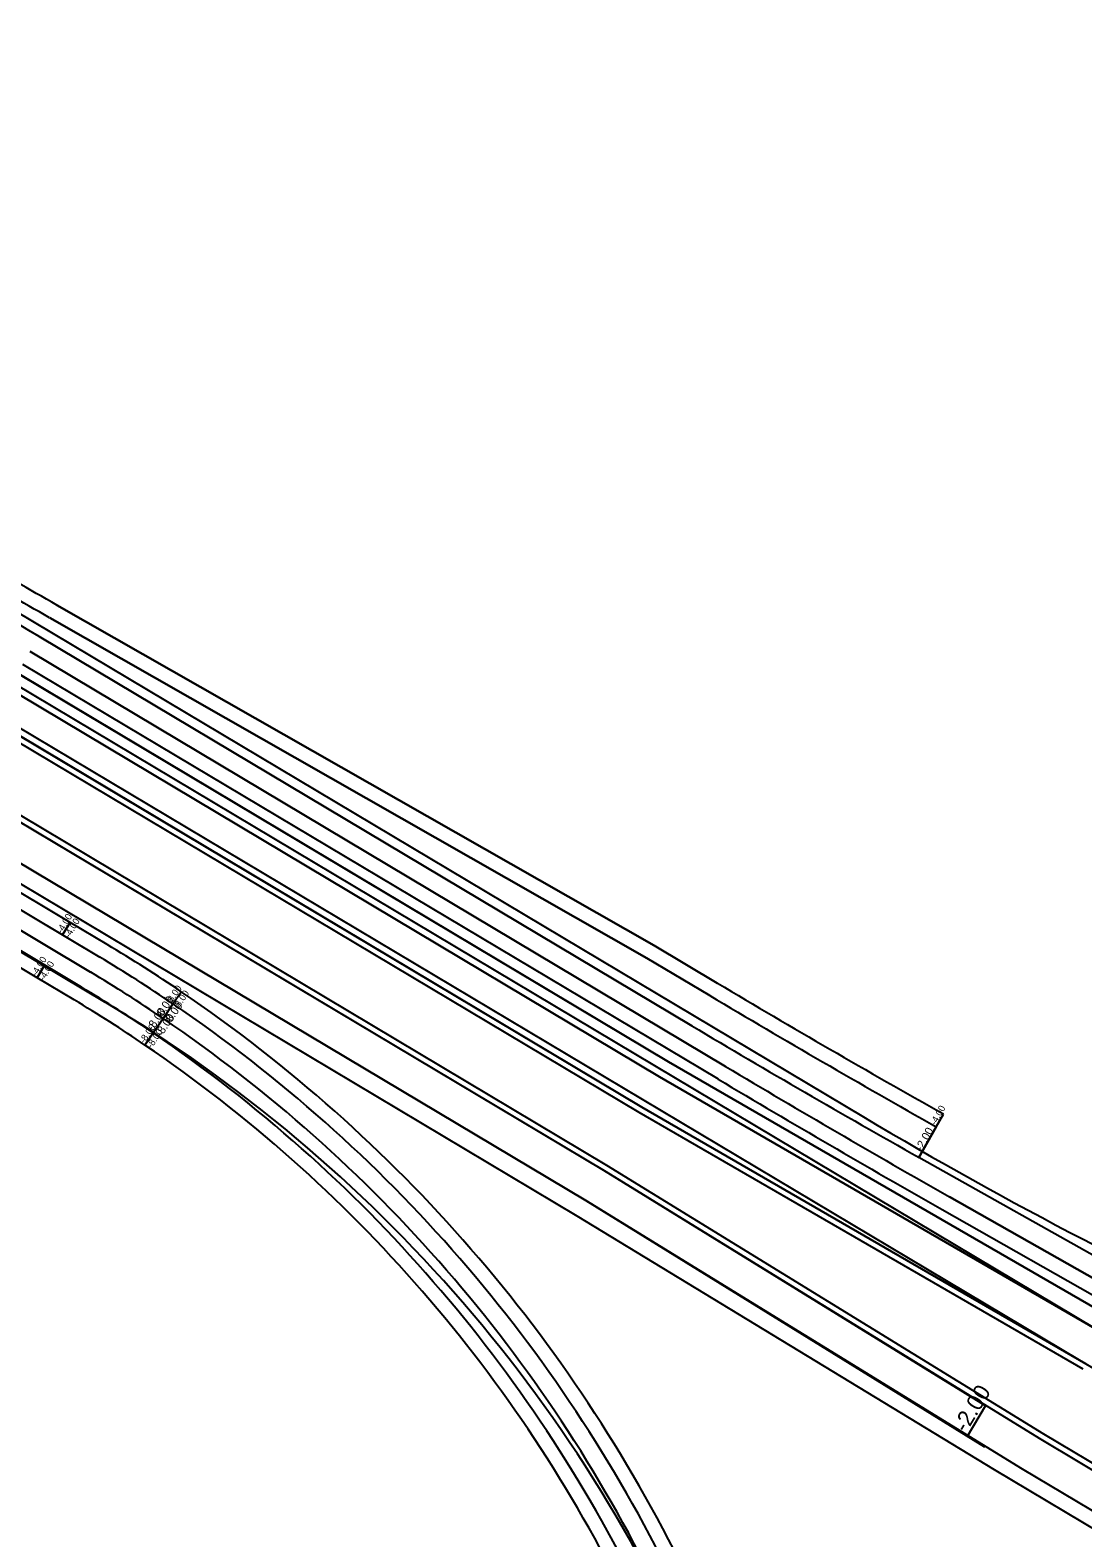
# Model space of a CAD drawing. Extents: x 2342222 to 2351711, y 366548 to 372860.
# Drawn here: x 2347894 to 2348613, y 368410 to 369439 of the extents above; entities that cross this region are included whole.
import ezdxf

# ---------------------------------------------------------------- set-up
doc = ezdxf.new("R2010")
doc.units = 0
for name, color, linetype in [('RD_HC_Cl', 7, 'Continuous'), ('RD_PD_Final_LnLine', 7, 'Continuous'), ('RD_PD_PaveShd', 7, 'Continuous'), ('RD_PD_SuperShp_BL_EB_526', 7, 'Continuous'), ('RD_PD_SuperShp_BL_WB_526', 7, 'Continuous'), ('RD_PD_SuperShp_EB_526', 7, 'Continuous'), ('RD_PD_SuperShp_REL_LINE-3', 7, 'Continuous'), ('RD_PD_SuperShp_Rel_Line-4', 7, 'Continuous'), ('RD_PD_SuperShp_WB_526', 7, 'Continuous')]:
    doc.layers.add(name, color=color, linetype=linetype)

msp = doc.modelspace()

# ---------------------------------------------------------------- linework, layer by layer
at = {"layer": 'RD_HC_Cl'}
msp.add_line((2346606.5, 369804.5), (2348463.1, 368696.8), dxfattribs=at)
msp.add_line((2346606.5, 369804.5), (2348463.1, 368696.8), dxfattribs=at)
msp.add_arc((2349949, 371187.2), 2900, 239.1785, 245.9774, dxfattribs=at)
msp.add_arc((2349949, 371187.2), 2900, 239.1785, 245.9774, dxfattribs=at)
at = {"layer": 'RD_PD_Final_LnLine'}
msp.add_line((2346236.7, 369794.6), (2347945.2, 368775.3), dxfattribs=at)
msp.add_line((2346236.7, 369794.6), (2347945.2, 368775.3), dxfattribs=at)
msp.add_arc((2347432.8, 367916.5), 1000, 22.4559, 59.1785, dxfattribs=at)
msp.add_arc((2347432.8, 367916.5), 1000, 22.4559, 59.1785, dxfattribs=at)
at = {"layer": 'RD_PD_PaveShd'}
for p, q in [((2347103.3, 369419.8), (2348309.7, 368700)), ((2347580.8, 369181.5), (2348330, 368734.5)), ((2348330, 368734.5), (2348633, 368559.4)), ((2348309.8, 368700), (2348612.7, 368524.9))]:
    msp.add_line(p, q, dxfattribs=at)
at = {"layer": 'RD_PD_SuperShp_BL_EB_526'}
for p, q in [((2348273.5, 368639.7), (2346277, 369830.9)), ((2346270.8, 369820.6), (2348267.4, 368629.4)), ((2346351.1, 369814.6), (2348286, 368660.2)), ((2348273.5, 368639.7), (2346338.8, 369794)), ((2347079.5, 369380), (2348286, 368660.2)), ((2348288, 368663.7), (2347081.6, 369383.5)), ((2348286, 368660.2), (2348584, 368476.8)), ((2348286, 368660.2), (2348584, 368476.8)), ((2348586.1, 368480.2), (2348288, 368663.7)), ((2348571.6, 368456.3), (2348273.5, 368639.7)), ((2348571.6, 368456.3), (2348273.5, 368639.7)), ((2348267.4, 368629.4), (2348552.3, 368456.1)), ((2348584, 368476.8), (2351064, 366997.1)), ((2348584, 368476.8), (2349219.5, 368097.6)), ((2349221.6, 368101.1), (2348586.1, 368480.2)), ((2348552.3, 368456.1), (2348815.4, 368299.2)), ((2351051.7, 366976.5), (2348571.6, 368456.3)), ((2348820.5, 368307.8), (2348571.6, 368456.3))]:
    msp.add_line(p, q, dxfattribs=at)
at = {"layer": 'RD_PD_SuperShp_BL_WB_526'}
for p, q in [((2348323.9, 368724.2), (2346306.8, 369927.7)), ((2346294.5, 369907), (2348311.8, 368703.5)), ((2347103.3, 369419.8), (2348309.8, 368700)), ((2348311.8, 368703.5), (2347105.3, 369423.3)), ((2348330, 368734.5), (2347580.8, 369181.5)), ((2347574.6, 369171.2), (2348323.9, 368724.2)), ((2348633, 368559.4), (2348330, 368734.5)), ((2348626.9, 368549), (2348323.9, 368724.2)), ((2348323.9, 368724.2), (2348626.9, 368549)), ((2348309.8, 368700), (2348612.7, 368524.9)), ((2348311.8, 368703.5), (2348614.8, 368528.3)), ((2348614.8, 368528.3), (2348311.8, 368703.5))]:
    msp.add_line(p, q, dxfattribs=at)
at = {"layer": 'RD_PD_SuperShp_EB_526'}
for p, q in [((2348285.9, 368660.3), (2346335.9, 369823.7)), ((2346323.3, 369803.3), (2348273.5, 368639.7)), ((2346323.6, 369803.1), (2348273.5, 368639.7)), ((2348546.3, 368499.6), (2348285.9, 368660.3)), ((2348273.5, 368639.7), (2348545.7, 368471.7)), ((2348273.5, 368639.7), (2348534, 368479)), ((2348534, 368479), (2348546.3, 368499.6))]:
    msp.add_line(p, q, dxfattribs=at)
at = {"layer": 'RD_PD_SuperShp_REL_LINE-3'}
for p, q in [((2347921.7, 368829.6), (2346247.5, 369828.4)), ((2346242.4, 369819.8), (2347916.5, 368821)), ((2346323.7, 369743.4), (2347904.2, 368800.4)), ((2347899.1, 368791.8), (2346318.6, 369734.8)), ((2347877.9, 368844), (2347941.8, 368805.9)), ((2347935.6, 368795.6), (2347871.8, 368833.7)), ((2347871.8, 368833.7), (2347935.6, 368795.6)), ((2347929.5, 368785.3), (2347865.6, 368823.4)), ((2347916.5, 368821), (2347921.7, 368829.6)), ((2347921.7, 368829.6), (2347916.5, 368821)), ((2347946.9, 368814.5), (2347921.7, 368829.6)), ((2347916.5, 368821), (2347941.8, 368805.9)), ((2347904.2, 368800.4), (2347899.1, 368791.8)), ((2347899.1, 368791.8), (2347904.2, 368800.4)), ((2347924.4, 368776.7), (2347899.1, 368791.8)), ((2347904.2, 368800.4), (2347929.5, 368785.3)), ((2347991.8, 368774.1), (2347997.4, 368782.3)), ((2347991.8, 368774.1), (2347997.4, 368782.3)), ((2347991.8, 368774.1), (2347985.1, 368764.1)), ((2347991.8, 368774.1), (2347985.1, 368764.1)), ((2347985.1, 368764.1), (2347978.3, 368754.2)), ((2347978.3, 368754.2), (2347985.1, 368764.1)), ((2347978.3, 368754.2), (2347972.7, 368745.9)), ((2347972.7, 368745.9), (2347978.3, 368754.2))]:
    msp.add_line(p, q, dxfattribs=at)
for radius, start, end in [(1022, 55.8206, 59.1785), (1012, 55.8206, 59.1785), (1012, 55.8206, 59.1785), (1000, 55.8206, 59.1785), (1000, 55.8206, 59.1785), (988, 55.8206, 59.1785), (988, 55.8206, 59.1785), (1022, 26.0841, 55.8206), (978, 55.8206, 59.1785), (1012, 26.0841, 55.8206), (1012, 26.0841, 55.8206), (1000, 26.0841, 55.8206), (1000, 26.0841, 55.8206), (988, 26.0841, 55.8206), (988, 26.0841, 55.8206), (978, 26.0841, 55.8206)]:
    msp.add_arc((2347423.3, 367936.8), radius, start, end, dxfattribs=at)
at = {"layer": 'RD_PD_SuperShp_Rel_Line-4'}
for p, q in [((2347912.6, 369046.2), (2348320.3, 368813.9)), ((2348320.3, 368813.9), (2347912.6, 369046.2)), ((2348315.2, 368805.2), (2347907.7, 369037.5)), ((2347907.7, 369037.5), (2348315.2, 368805.2)), ((2347900.5, 369024.7), (2348345.9, 368759)), ((2347900.5, 369024.7), (2348345.9, 368759)), ((2348345.9, 368759), (2347900.5, 369024.7)), ((2347894.4, 369014.4), (2348368.9, 368731.3)), ((2348368.9, 368731.3), (2347894.4, 369014.4)), ((2347894.4, 369014.4), (2348368.9, 368731.3)), ((2347889.2, 369005.8), (2348363.8, 368722.7)), ((2347889.2, 369005.8), (2348363.8, 368722.7)), ((2348320.3, 368813.9), (2348363.3, 368788.2)), ((2348363.3, 368788.2), (2348320.3, 368813.9)), ((2348358.2, 368779.6), (2348315.2, 368805.2)), ((2348315.2, 368805.2), (2348358.2, 368779.6)), ((2348512.7, 368690.1), (2348517.6, 368698.8)), ((2348512.7, 368690.1), (2348517.6, 368698.8)), ((2348512.7, 368690.1), (2348500.9, 368669.1)), ((2348506.8, 368679.6), (2348512.7, 368690.1)), ((2348500.9, 368669.2), (2348506.8, 368679.6)), ((2348827.2, 368485.6), (2348500.9, 368669.2)), ((2348962.5, 368409.5), (2348500.9, 368669.2)), ((2348955.1, 368396.3), (2348521.8, 368642.3)), ((2349153, 368283.9), (2348521.8, 368642.3)), ((2348521.8, 368642.3), (2348955.1, 368396.3)), ((2348516.8, 368633.6), (2349148.1, 368275.2))]:
    msp.add_line(p, q, dxfattribs=at)
for centre, radius, start, end in [((2343690.2, 361967.9), 8217.3, 59.17851, 61.01367), ((2343690.2, 361967.9), 8217.3, 59.17851, 61.01367), ((2343690.2, 361967.9), 8217.3, 59.17851, 61.01367), ((2343906.6, 362012.6), 8084.4, 60.3362, 61.25045), ((2343906.6, 362012.6), 8084.4, 60.3362, 61.25045), ((2343906.6, 362012.6), 8094.4, 60.3362, 61.25011), ((2343906.6, 362012.6), 8094.4, 60.3362, 61.25011), ((2351938.6, 374780.7), 6978, 239.17851, 240.6428), ((2351938.6, 374780.7), 6978, 239.17851, 240.6428), ((2351938.6, 374780.7), 6988, 239.17851, 240.6428), ((2351938.6, 374780.7), 6988, 239.17851, 240.6428), ((2351938.6, 374780.7), 7012, 239.17851, 240.64271), ((2351938.6, 374780.7), 7012, 239.17851, 240.64271), ((2352567.6, 375768.6), 8194.7, 239.17851, 240.4151), ((2352567.6, 375768.6), 8194.7, 239.17851, 240.4151), ((2352567.6, 375768.6), 8194.7, 239.17851, 240.4151), ((2352567.6, 375768.6), 8204.7, 239.17851, 240.4151), ((2352567.6, 375768.6), 8204.7, 239.17851, 240.4151)]:
    msp.add_arc(centre, radius, start, end, dxfattribs=at)
at = {"layer": 'RD_PD_SuperShp_WB_526'}
msp.add_line((2346189.9, 369975), (2349293.2, 368123.5), dxfattribs=at)
msp.add_lwpolyline([(2349305.5, 368144.1), (2347116.8, 369450), (2347110.7, 369439.7), (2346196.1, 369985.3)], dxfattribs=at)

# ---------------------------------------------------------------- texts
at = {"layer": 'RD_PD_SuperShp_EB_526'}
msp.add_text('-2.00', height=11.04, rotation=59.1785, dxfattribs=at).set_placement((2348533.1, 368480.7))
at = {"layer": 'RD_PD_SuperShp_REL_LINE-3'}
for s, height, rotation, p in [('-4.00', 4.6, 59.1785, (2347916.1, 368821.7)), ('-4.00', 4.6, 59.1785, (2347921.3, 368818.6)), ('-4.00', 4.6, 59.1785, (2347898.7, 368792.5)), ('-4.00', 4.6, 59.1785, (2347903.9, 368789.4)), ('8.00', 4.6, 55.8206, (2347991.4, 368774.8)), ('8.00', 4.6, 55.8206, (2347996.4, 368771.4)), ('-8.00', 5.52, 55.8206, (2347977.9, 368755.1)), ('8.00', 5.52, 55.8206, (2347984.6, 368765)), ('8.00', 5.52, 55.8206, (2347990.6, 368760.9)), ('-8.00', 5.52, 55.8206, (2347983.8, 368751)), ('-8.00', 4.6, 55.8206, (2347972.3, 368746.6)), ('-8.00', 4.6, 55.8206, (2347977.3, 368743.3))]:
    msp.add_text(s, height=height, rotation=rotation, dxfattribs=at).set_placement(p)
at = {"layer": 'RD_PD_SuperShp_Rel_Line-4'}
for s, height, rotation, p in [('-4.00', 4.6, 60.6428, (2348512.3, 368690.8)), ('-2.00', 5.52, 60.6412, (2348502.8, 368673))]:
    msp.add_text(s, height=height, rotation=rotation, dxfattribs=at).set_placement(p)

doc.saveas('drawing.dxf')
